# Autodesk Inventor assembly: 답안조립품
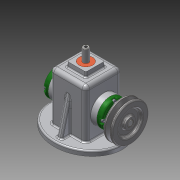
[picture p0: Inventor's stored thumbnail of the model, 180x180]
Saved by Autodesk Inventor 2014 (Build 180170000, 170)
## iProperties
Created: 2017-07
Part Number: 답안조립품
Document SubType Name: Assembly
Designer: user
Author: user
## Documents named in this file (16)
- C:\Users\user\Desktop\470708V1014\답안조립품.iam
- C:\Users\user\Desktop\470708V1014\V벨트풀리.ipt
- C:\Users\user\Desktop\470708V1014\고정핀 1.2 x  8.ipt
- C:\Users\user\Desktop\470708V1014\뒤커버.ipt
- C:\Users\user\Desktop\470708V1014\링크.ipt
- C:\Users\user\Desktop\470708V1014\멈춤나사 M3x8.ipt
- C:\Users\user\Desktop\470708V1014\베어링 12 x 32 x 10.ipt
- C:\Users\user\Desktop\470708V1014\본체.ipt
- C:\Users\user\Desktop\470708V1014\볼트 M4 x 12.ipt
- C:\Users\user\Desktop\470708V1014\부시.ipt
- C:\Users\user\Desktop\470708V1014\슬라이드.ipt
- C:\Users\user\Desktop\470708V1014\앞커버.ipt
- C:\Users\user\Desktop\470708V1014\오일실 12 25 7.ipt
- C:\Users\user\Desktop\470708V1014\키 4 x 4 x 10.ipt
- C:\Users\user\Desktop\470708V1014\편심축.ipt
- C:\Users\user\Desktop\470708V1014\핀 5 x 18.ipt
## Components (3 placed, 3 different names)
1. V벨트풀리:2
2. 고정핀 1.2 x  8:2
3. 핀 5 x 18:2
